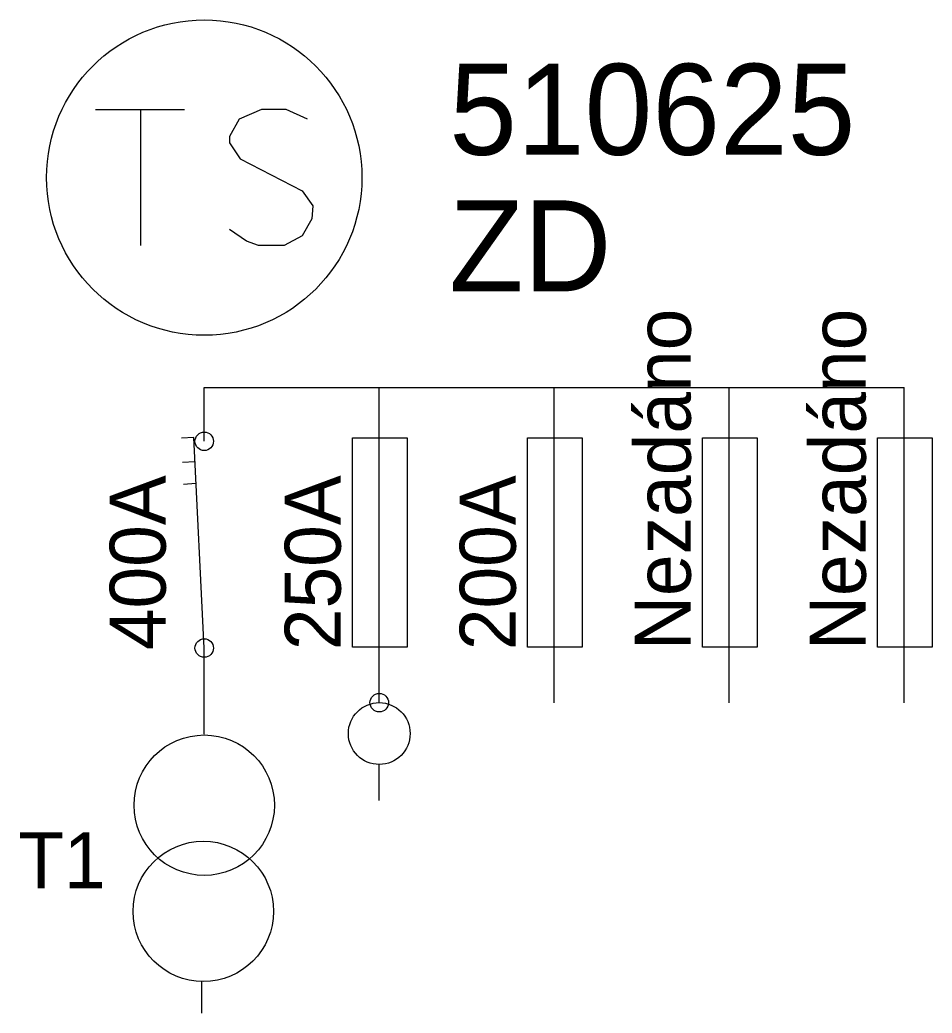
# Model space of a CAD drawing. Extents: x -544781 to -541582, y -1198995 to -1196857.
# Drawn here: x -543899.68 to -543873.61, y -1197878.46 to -1197850.08 of the extents above; entities that cross this region are included whole.
import ezdxf

# ---------------------------------------------------------------- set-up
doc = ezdxf.new("R2010")
doc.units = 0
for name, color, linetype in [('Implicitní', 7, 'Continuous'), ('Vrstva 1', 7, 'Continuous'), ('Vrstva 2', 7, 'Continuous'), ('Vrstva 3', 7, 'Continuous')]:
    doc.layers.add(name, color=color, linetype=linetype)

# ---------------------------------------------------------------- blocks, each defined once
blk = doc.blocks.new('CONSUM')
at = {"layer": 'Implicitní'}
blk.add_line((0, -2.797), (0, -1.767), dxfattribs=at)
blk.add_circle((0, -0.883), 0.883, dxfattribs=at)
blk = doc.blocks.new('STATIO4')
at = {"layer": 'Vrstva 1'}
for p, q in [((-3.106, 1.943), (-0.566, 1.943)), ((-1.821, 1.943), (-1.821, -1.943))]:
    blk.add_line(p, q, dxfattribs=at)
blk.add_lwpolyline([(2.953, 1.668), (2.341, 1.943), (1.637, 1.943), (0.995, 1.668), (0.719, 1.178), (0.719, 0.994), (1.025, 0.536), (2.8, -0.382), (3.106, -0.811), (3.076, -1.178), (2.8, -1.668), (2.28, -1.943), (1.546, -1.943), (1.209, -1.821), (0.719, -1.484)], dxfattribs=at)
blk.add_circle((0, 0), 4.505, dxfattribs=at)
blk = doc.blocks.new('TRAPLC')
at = {"layer": 'Vrstva 1'}
for p, q in [((0, -0.902), (0, 0)), ((-0.072, -8.87), (-0.072, -7.968))]:
    blk.add_line(p, q, dxfattribs=at)
for centre in [(0, -2.929), (-0.026, -5.964)]:
    blk.add_circle(centre, 2.005, dxfattribs=at)
blk = doc.blocks.new('TAPV18S1')
at = {"layer": 'Implicitní'}
blk.add_lwpolyline([(-0.766, -1.438), (0.795, -1.438), (0.795, -7.414), (-0.766, -7.414)], close=True, dxfattribs=at)
at = {"layer": 'Vrstva 1'}
blk.add_line((0, -9.01), (0, 0), dxfattribs=at)
blk = doc.blocks.new('TAPVN1S1')
at = {"layer": 'Implicitní'}
for p, q in [((0, -1.534), (0, 0)), ((-0.301, -1.427), (-0.653, -1.447)), ((0, -7.44), (-0.301, -1.427)), ((-0.267, -2.124), (-0.62, -2.144)), ((-0.242, -2.744), (-0.595, -2.764)), ((0, -9.01), (0, -7.44))]:
    blk.add_line(p, q, dxfattribs=at)
for centre in [(0, -1.534), (0, -7.44)]:
    blk.add_circle(centre, 0.265, dxfattribs=at)
blk = doc.blocks.new('TAPV1')
at = {"layer": 'Vrstva 1'}
blk.add_circle((0, 0), 0.265, dxfattribs=at)

msp = doc.modelspace()

# ---------------------------------------------------------------- linework, layer by layer
at = {"layer": 'Vrstva 3'}
msp.add_lwpolyline([(-543894.41, -1197860.59), (-543874.41, -1197860.59)], dxfattribs=at)

# ---------------------------------------------------------------- block references
at = {"layer": 'Vrstva 2'}
msp.add_blockref('CONSUM', (-543889.41, -1197869.59), dxfattribs=at)
at = {"layer": 'Vrstva 3'}
for name, p in [('STATIO4', (-543894.41, -1197854.59)), ('TAPVN1S1', (-543894.41, -1197860.59)), ('TAPV18S1', (-543889.41, -1197860.59)), ('TAPV18S1', (-543884.41, -1197860.59)), ('TAPV18S1', (-543879.41, -1197860.59)), ('TAPV18S1', (-543874.41, -1197860.59)), ('TAPV1', (-543889.41, -1197869.59)), ('TRAPLC', (-543894.41, -1197869.59))]:
    msp.add_blockref(name, p, dxfattribs=at)

# ---------------------------------------------------------------- texts
for s, height, p in [('510625', 2.6, (-543887.41, -1197853.94)), ('ZD', 2.6, (-543887.41, -1197857.84)), ('T1', 1.6, (-543899.725, -1197874.89))]:
    msp.add_text(s, height=height, dxfattribs=at).set_placement(p)
for s, p in [('Nezadáno', (-543880.51, -1197868.09)), ('Nezadáno', (-543875.51, -1197868.09)), ('400A', (-543895.51, -1197868.09)), ('250A', (-543890.51, -1197868.09)), ('200A', (-543885.51, -1197868.09))]:
    msp.add_text(s, height=1.6, rotation=90, dxfattribs=at).set_placement(p)

doc.saveas('drawing.dxf')
